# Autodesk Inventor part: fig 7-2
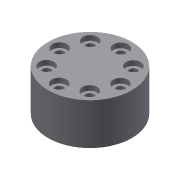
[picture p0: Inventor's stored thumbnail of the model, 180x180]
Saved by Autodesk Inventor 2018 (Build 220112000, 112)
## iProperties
Created: 2004-05
Part Number: fig 7-2
Document SubType Name: Modeling
Designer: CADCIM Technologies
Manufacturer: Standard
Standards Organization: Custom
Density: 1 g/cm^3
Material: Generic
Appearance: Default
Author: CADCIM Technologies
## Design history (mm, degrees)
sketch "Sketch1"
  geometry: C1 r 17.175 at (0, 0)
  constraints: 1 centre point
extrude "Extrusion1" new body sketch "Sketch1" distance "d0" = 17; taper "d1" = 0 deg
sketch "Sketch2"
  geometry: 1 further point
hole "Hole1" sketch "Sketch2" at (12.571, -0.074) diameter "d2" = 3.5; stored, may be unused: countersink angle "d6" = 90 deg, drill point angle "d8" = 118 deg; dims "d3" = 6, "d4" = 6, "d5" = 2, "d7" = 8
pattern_circular "Circular Pattern1" dims angle "d11" = 360 deg
body "Solid1"
